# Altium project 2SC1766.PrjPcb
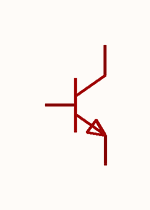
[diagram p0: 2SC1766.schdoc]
1 sheet, 1 parts. Net scope: global (net labels, ports and power ports of the same name join across sheets).

## Sheet 2SC1766.schdoc
size 127 x 101 mm

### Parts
Q?  2sc1766  [SOT-89-3L_L4.5-W2.5-P1.50-LS4.1-BR]  (value not drawn)

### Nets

Not connected (* = marked no-connect by the designer): Q? 1(B) 2(C) 3(E)

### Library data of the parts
Q? = 2sc1766: 晶体管类型:NPN;集电极电流(Ic):2A;集射极击穿电压(Vceo):50V;耗散功率(Pd):500mW;直流电流增益(hFE):390;; Manufacturer: CJ(江苏长电/长晶); AddInBom: yes; ModelId: fb691090912a49e3bd79f7e2a6bd732b; ModelTransform: 157.48,177.165,0,0,0,0,-23.622,0,0; type: NPN; Current - Collector(Ic): 2A; Collector - Emitter Voltage VCEO: 50V; Pd - Power Dissipation: 500mW; DC Current Gain: 390; Transition frequency(fT): 120MHz; Current - Collector Cutoff: 100nA; Vce Saturation(VCE(sat)): 500mV; Emitter-Base Voltage(Vebo): 5V; Number: 1个NPN; Configuration: 独立式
